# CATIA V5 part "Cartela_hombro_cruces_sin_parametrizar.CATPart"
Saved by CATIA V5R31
Part number: Cartela_param_pilar_dintel
Material "PLA": density 1240 kg/m3, Young's modulus 3.2e+09 Pa, Poisson ratio 0.331, thermal expansion 6.84e-05 1/K
Bounding box of the stored display mesh (mm): x -3.75 to 19.494, y -3.75 to 22.595, z -2 to 2
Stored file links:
  C:\Users\super\Desktop\LEGO\Cartela_hombro_cruces_sin_parametrizar.CATPart
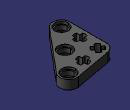
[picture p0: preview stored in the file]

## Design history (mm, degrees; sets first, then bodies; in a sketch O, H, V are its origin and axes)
Parameters
  Tipo_cartela = "pilar_dintel"
  Dist_pilares_estructura = 354.255 mm
  Long_dintel = 180 mm
  Diam_agujero = 5 mm
  N_lado_corto = 3
  Lado_cartela = 16 mm
  Espesor = 4 mm
  Angulo_cartela_pilar_dintel = 100.2497 deg {= acos((Dist_pilares_estructura/2)/Long_dintel)+90deg}
  Angulo_cartela_dintel_dintel = 159.5006 deg {= 2*(180deg-Angulo_cartela_pilar_dintel)}
  h = 10.2579 mm
  Altura_cartela = 10.2579 mm
  Angulo_cartela = 100.2497 deg
Set1 "REFERENCIAS"
  Plane1 "PLANO_CENTRAL": type OffsetPt, RefPlane XY plane of AxisSystem1, RefPoint vertex [element of Sketch1 | element of Sketch1]
  AxisSystem1: origin (0, 0, 0), X (1, 0, 0), Y (0, 1, 0), Z (0, 0, 1)
  Sketch1 "GUIA" on XY plane of AxisSystem1, origin (0, 0, 0), H (1, 0, 0), V (0, 1, 0)
    line L1 (0, 0) -> (0, 16)
    point P1 (0, 0)
    line L2 (0, 16) -> (15.7447, 18.847)
    point P3 (15.7447, 18.847)
    curve C1
    length L1 = 16 {= Lado_cartela}
    length L2 = 16 {= Lado_cartela}
    angle L1 L2 = 100.2497 {= Angulo_cartela}
    vertical: L1 V
    coincidence: P1 O
  Line1 "REF_LADO_LARGO": type PtPt, FirstPoint Sketch1.P3, SecondPoint vertex [YZ plane of AxisSystem1 | ZX plane of AxisSystem1 | XY plane of AxisSystem1]
  Point1 "PUNTO_MEDIO_LADO_LARGO": type OnCurve, Support Line1, Ratio 0.5
  Line2 "PERP_LADO_LARGO": type PtPt, FirstPoint vertex [element of Sketch1 | element of Sketch1], SecondPoint Point1
  Plane2: type OffsetPt, RefPlane start face of Pad1, RefPoint Sketch1.P3
  Point2: type Between, FirstPoint Sketch1.P3, SecondPoint vertex [element of Sketch1 | element of Sketch1], Ratio 0.5
  Plane3: type OffsetPt, RefPlane start face of Pad1, RefPoint Point2
  Plane4: type Angle, RefPlane Plane1, Direction Line2, Angle 90
  Point3: type Between, FirstPoint Sketch1.P3, SecondPoint vertex [element of Sketch1 | element of Sketch1], Ratio 0.5
  Plane5: type OffsetPt, RefPlane start face of Pad1, RefPoint Point3
Body1 (main body), material "PLA"
  Sketch2 "BASE" on Plane1, origin (0, 16, 0), H (1, 0, 0), V (0, 1, 0)
    arc A1 centre (0, 0) radius 3.75 from (-0.6673, 3.6902) to (-3.75, 0) ccw
    point P1 (0, 0)
    point P2 (0, -16)
    arc A2 centre (0, -16) radius 3.75 from (-3.75, -16) to (2.8779, -18.4042) ccw
    point P3 (15.7447, 2.847)
    arc A3 centre (15.7447, 2.847) radius 3.75 from (18.6226, 0.4428) to (15.0774, 6.5372) ccw
    projected point E1 (15.7447, 2.847) from Sketch1.P3
    projected point E2 (0, -16) from vertex [YZ plane of AxisSystem1 | ZX plane of AxisSystem1 | XY plane of AxisSystem1]
    line L1 (15.0774, 6.5372) -> (-0.6673, 3.6902)
    line L2 (18.6226, 0.4428) -> (2.8779, -18.4042)
    line L3 (-3.75, 0) -> (-3.75, -16)
    curve C1
    radius A3 = 3.75
    coincidence: P3 E1, P2 E2, P1 O
    tangency: L1 A3, L1 A1, L2 A3, L2 A2, L3 A1, L3 A2
    equal size: A1 A3, A3 A2
  Pad1 "CUERPO_BASE": profile Sketch2, direction (0, 0, 1), length 2 {= Espesor / 2}, mirrored extent
  Sketch3 "CRUZ" on Plane3, origin (7.8723, 17.4235, 0), H (-0.984, -0.1779, 0), V (-0.1779, 0.984, 0)
    line L1 (-1, 2.2913) -> (-1, 1)
    line L2 (-1, 1) -> (-2.2913, 1)
    line L3 (-2.2913, -1) -> (-1, -1)
    point P5 (-1, -1)
    line L4 (-1, -1) -> (-1, -2.2913)
    line L5 (1, -2.2913) -> (1, -1)
    line L6 (1, -1) -> (2.2913, -1)
    point P9 (2.2913, -1)
    point P10 (2.2913, 1)
    line L7 (2.2913, 1) -> (1, 1)
    point P11 (1, 1)
    line L8 (1, 1) -> (1, 2.2913)
    projected line E1 (-8, 0) -> (8, 0) from Sketch1.L2
    projected point E2 (0, 0) from Point2
    projected point E3 (0, 0) from Point2
    arc A1 centre (0, 0) radius 2.5 from (1, 2.2913) to (-1, 2.2913) ccw
    point P14 (2.2913, -1)
    arc A2 centre (0, 0) radius 2.5 from (-2.2913, 1) to (-2.2913, -1) ccw
    arc A3 centre (0, 0) radius 2.5 from (2.2913, -1) to (2.2913, 1) ccw
    arc A4 centre (0, 0) radius 2.5 from (-1, -2.2913) to (1, -2.2913) ccw
    curve C1
    radius A1 = 2.5
    distance L3 L2 = 2
    distance L8 L1 = 2
    vertical: L1 V, L4 V, L5 V, L8 V
    horizontal: L2 H, L3 H, L6 H, L7 H
    coincidence: P5 L1, P10 L2, P11 L5, A1 P14, P14 L3, P9 A1, A1 A2, A2 A3, A2 A4
    symmetry: L7 L6 E1, L3 L2 E1
    equidistance: L8 L1 E2, L5 L4 E3
    concentricity: A1 O
  Pocket1 "CRUZ": profile Sketch3, direction (0, 0, -1), through (limit type 3), opposite side through (limit type 3)
  Mirror1 "CRUZ_SIMETRICA": of Pocket1, about Plane4
  Sketch4 on Plane1, origin (0, 16, 0), H (-0.6411, -0.7674, 0), V (-0.7674, 0.6411, 0)
    construction line L1 through (0, 0) direction (0, 1)
    line L2 (-1, 2.2913) -> (-1, 1)
    construction line L3 through (0, 0) direction (1, 0)
    line L4 (-1, 1) -> (-2.2913, 1)
    point P1 (-1, -1)
    line L5 (-2.2913, -1) -> (-1, -1)
    line L6 (-1, -1) -> (-1, -2.2913)
    line L7 (1, -2.2913) -> (1, -1)
    line L8 (1, -1) -> (2.2913, -1)
    point P2 (2.2913, 1)
    point P3 (1, 1)
    line L9 (2.2913, 1) -> (1, 1)
    line L10 (1, 1) -> (1, 2.2913)
    point P4 (2.2913, -1)
    arc A1 centre (0, 0) radius 2.5 from (1, 2.2913) to (-1, 2.2913) ccw
    point P5 (0, 0)
    point P6 (2.2913, -1)
    arc A2 centre (0, 0) radius 2.5 from (-2.2913, 1) to (-2.2913, -1) ccw
    arc A3 centre (0, 0) radius 2.5 from (2.2913, -1) to (2.2913, 1) ccw
    arc A4 centre (0, 0) radius 2.5 from (-1, -2.2913) to (1, -2.2913) ccw
    curve C1
    distance L5 L4 = 2
    distance L10 L2 = 2
    radius A1 = 2.5
    vertical: L2 L1, L6 L1, L7 L1, L10 L1
    horizontal: L4 L3, L5 L3, L8 L3, L9 L3
    coincidence: P1 L2, P2 L4, P3 L7, A1 P4, P4 L5, P6 A1, A1 A2, A2 A3, A2 A4
    concentricity: A1 P5, A2 O
    equal size: A1 A3, A3 A4, A4 A2
    equidistance: L10 L2 O, L4 L5 O
    symmetry: L10 L2 V, L8 L9 H
  Pocket2 "CRUZ_CENTRAL": profile Sketch4, direction (0, 0, -1), through (limit type 3), opposite side through (limit type 3)
  Sketch5 on start face of Pad1, origin (-0.4555, -2.4789, -2), H (1, 0, 0), V (0, -1, 0)
    point P1 (0.4555, -2.4789)
    reference projected arc E1 centre (0.4555, -2.4789) radius 3.75 from (3.3334, -0.0748) to (-3.2945, -2.4789) ccw from edge [start face of Pad1 | face of Pad1 from Sketch2.A2]
    concentricity: E1 P1
  Hole1 "AGUJERO": placed by Sketch5, at (0, 0, -2) direction (0, 0, 1), diameter 5, through (limit type 3), counterbore diameter 6, counterbore depth 1
  Mirror2: of Hole1, about XY plane of AxisSystem1
  RectPattern1: of Hole1, direction 1 instances 3, spacing 12.26, along Line1 reversed, direction 2 instances 3, spacing 4
  Mirror3: of RectPattern1, about Plane1
Relations
  h = (Lado_cartela )* (sin(90deg-((Angulo_cartela_pilar_dintel )/2))) (deactivated)
  rule "Altura_cartela":
    /*Rule created by Jesus Arozamena*/
    if h >8mm	/*= Diam_agujero*2*/
    	Altura_cartela = h
    else
    	Altura_cartela = 0mm
  rule "Angulo_cartela":
    /*Rule created by Jesus Arozamena*/
    if Tipo_cartela  == "pilar_dintel"
    	Angulo_cartela  = Angulo_cartela_pilar_dintel
    else
    	Angulo_cartela  = Angulo_cartela_dintel_dintel
  rule "Existencia_agujero_lado_largo":
    /*Rule created by Jesus Arozamena 20/12/2023*/
    if Tipo_cartela =="dintel_dintel"
    	h = 10
    else
    	h = (Lado_cartela )* (sin(90deg-((Angulo_cartela_pilar_dintel )/2)))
